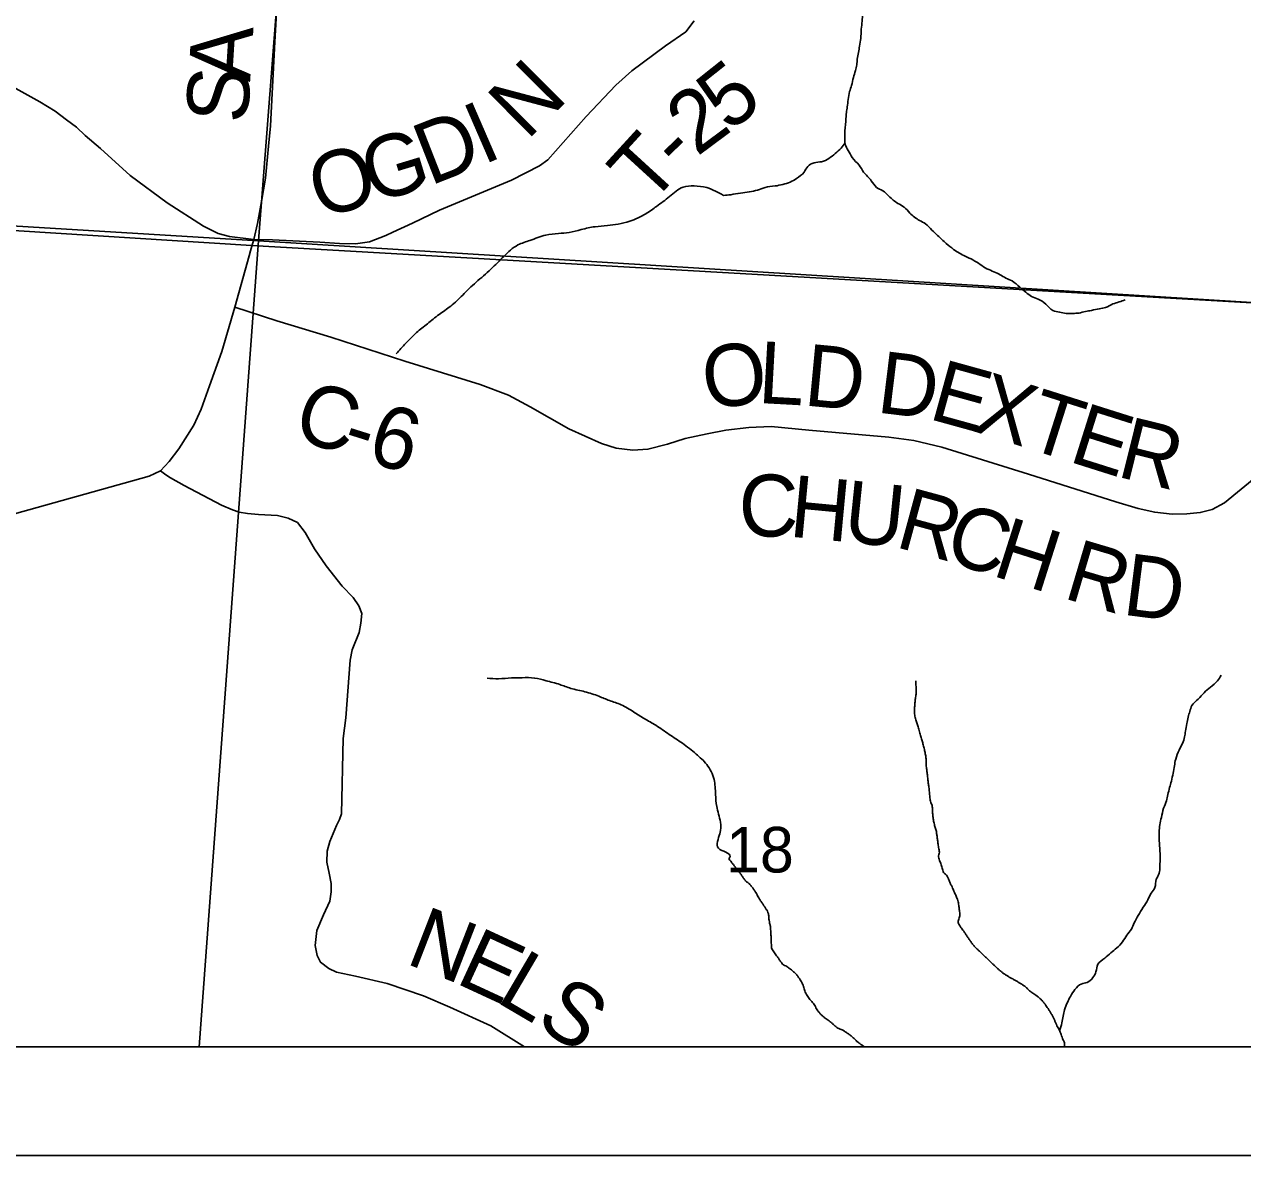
# Model space of a CAD drawing. Extents: x -13.7 to 34, y 0 to 32.3.
# Drawn here: x 28.447 to 29.565, y 14 to 15.038 of the extents above; entities that cross this region are included whole.
import ezdxf

# ---------------------------------------------------------------- set-up
doc = ezdxf.new("R2010")
doc.units = 0
for name, color, linetype in [('GM_X_Corporation', 7, 'Continuous'), ('GM_X_County_Road', 7, 'Continuous'), ('GM_X_County_Road_Text', 7, 'Continuous'), ('GM_X_Minor_River', 7, 'Continuous'), ('GM_X_Section_Text', 7, 'Continuous'), ('GM_X_Township_Road', 7, 'Continuous'), ('GM_X_Township_Road_Text', 7, 'Continuous'), ('SH_Data', 7, 'Continuous')]:
    doc.layers.add(name, color=color, linetype=linetype)

msp = doc.modelspace()

# ---------------------------------------------------------------- linework, layer by layer
at = {"layer": 'GM_X_Corporation'}
for points in [[(25.5491, 14.1), (30.3167, 14.1), (30.3167, 20.877), (30.2775, 20.8796), (29.9598, 20.9), (26.0026, 20.9)], [(27.6886, 14.8962), (28.6553, 14.8354), (29.7019, 14.7755), (30.3167, 14.7354), (30.3167, 20.877), (30.2775, 20.8796), (29.9598, 20.9), (26.0026, 20.9)]]:
    msp.add_lwpolyline(points, dxfattribs=at)
for points in [[(27.73, 15.9158), (28.7402, 15.8562), (28.6615, 14.8398), (27.6593, 14.9006)], [(28.7402, 15.8562), (28.7512, 15.8567), (29.7549, 15.7939), (29.6625, 14.7774), (28.6615, 14.8398)], [(25.5491, 14.1), (30.3167, 14.1), (30.3167, 14.7354), (29.7019, 14.7755), (28.6553, 14.8354), (27.6886, 14.8962), (26.847, 14.9399), (26.2581, 14.9774), (25.6174, 15.0182)], [(27.607, 14.1), (28.6073, 14.1), (28.6615, 14.8398), (27.6593, 14.9006)], [(28.6073, 14.1), (29.6122, 14.1), (29.6625, 14.7774), (28.6615, 14.8398)]]:
    msp.add_lwpolyline(points, close=True, dxfattribs=at)
at = {"layer": 'GM_X_County_Road'}
for points in [[(28.6572, 14.8408), (28.6606, 14.8556), (28.6643, 14.8757), (28.6682, 14.8973), (28.6709, 14.9265), (28.6726, 14.9453), (28.6766, 15.0223), (28.6792, 15.0656)], [(28.4362, 14.9809), (28.4609, 14.9672), (28.4749, 14.9588), (28.4852, 14.9507), (28.4945, 14.944), (28.5025, 14.9364), (28.5165, 14.9244), (28.5437, 14.8997), (28.5779, 14.8745), (28.611, 14.853), (28.6247, 14.8465), (28.6351, 14.8437), (28.6572, 14.8408)], [(28.6543, 14.8305), (28.6555, 14.8349), (28.6572, 14.8408)], [(28.64, 14.7787), (28.653, 14.826), (28.6543, 14.8305)], [(28.4221, 14.5848), (28.5611, 14.6235), (28.5717, 14.6286), (28.5796, 14.637), (28.5886, 14.6488), (28.6023, 14.6706), (28.6091, 14.6853), (28.6167, 14.7067), (28.6279, 14.7382), (28.64, 14.7787)], [(28.64, 14.7787), (28.6785, 14.7663), (28.7279, 14.7511), (28.796, 14.7291), (28.8651, 14.7078), (28.8913, 14.698), (28.9111, 14.6873), (28.9466, 14.6672), (28.9765, 14.6537), (28.99, 14.6495), (29.0052, 14.6474), (29.0192, 14.6483), (29.0372, 14.653), (29.0533, 14.6583), (29.0736, 14.6625), (29.0906, 14.6658), (29.1119, 14.6684), (29.1322, 14.6693), (29.1668, 14.6658), (29.2403, 14.6593), (29.2632, 14.6565), (29.2891, 14.6504), (29.3685, 14.6254), (29.4487, 14.6001), (29.4693, 14.5941), (29.4845, 14.5906), (29.5006, 14.5888), (29.5139, 14.589), (29.5263, 14.5902), (29.5373, 14.593), (29.5487, 14.5993), (29.5793, 14.6243)]]:
    msp.add_lwpolyline(points, dxfattribs=at)
at = {"layer": 'GM_X_Minor_River'}
for points in [[(29.3153, 15.2944), (29.3148, 15.2891), (29.3144, 15.283), (29.3143, 15.2754), (29.3127, 15.2686), (29.3111, 15.2625), (29.3077, 15.2557), (29.3038, 15.2493), (29.3003, 15.2441), (29.2984, 15.2384), (29.2983, 15.2262), (29.299, 15.2205), (29.2993, 15.2133), (29.3, 15.2076), (29.2999, 15.2008), (29.2987, 15.1951), (29.296, 15.1894), (29.2917, 15.1834), (29.2894, 15.1758), (29.2885, 15.1637), (29.2881, 15.1569), (29.2884, 15.1508), (29.2898, 15.1455), (29.2894, 15.139), (29.2897, 15.1337), (29.2897, 15.1272), (29.2888, 15.12), (29.2869, 15.1144), (29.2818, 15.1064), (29.2765, 15.1038), (29.2697, 15.102), (29.2621, 15.0998), (29.2541, 15.0961), (29.2483, 15.0927), (29.2422, 15.0878), (29.2353, 15.083), (29.2296, 15.0811), (29.2228, 15.0786), (29.2182, 15.0733), (29.2173, 15.0672), (29.2161, 15.0619), (29.2168, 15.0555), (29.2164, 15.0482), (29.2159, 15.0414), (29.2151, 15.0338), (29.2146, 15.0255), (29.2134, 15.0183), (29.2126, 15.0126), (29.2114, 15.0065), (29.211, 15.0012), (29.2098, 14.9959), (29.2078, 14.9895), (29.2062, 14.9823), (29.2043, 14.9766), (29.2031, 14.9694), (29.2022, 14.9626), (29.2014, 14.9573), (29.201, 14.952), (29.2001, 14.9406), (29.2, 14.9345), (29.2004, 14.9281), (29.203, 14.9227), (29.2067, 14.9162), (29.2131, 14.909), (29.2172, 14.9028), (29.2243, 14.8948), (29.2292, 14.8887), (29.2348, 14.8856), (29.2405, 14.8806), (29.2487, 14.874), (29.2544, 14.8706), (29.2597, 14.8652), (29.2687, 14.8583), (29.274, 14.8552), (29.28, 14.8494), (29.2852, 14.8445), (29.2931, 14.8372), (29.2999, 14.8318), (29.3052, 14.8283), (29.3105, 14.8256), (29.3176, 14.8221), (29.3244, 14.8179), (29.3305, 14.814), (29.3369, 14.8113), (29.3425, 14.8086), (29.3478, 14.8055), (29.3535, 14.8028), (29.3606, 14.797), (29.3663, 14.7924), (29.3715, 14.7885), (29.3776, 14.7862), (29.3844, 14.7816), (29.3911, 14.7758), (29.3972, 14.7742), (29.4033, 14.773), (29.4093, 14.773), (29.415, 14.7733)], [(27.5226, 15.1494), (27.5325, 15.144), (27.5426, 15.1352), (27.5528, 15.1283), (27.5649, 15.1222), (27.574, 15.11), (27.5765, 15.0967), (27.5795, 15.086), (27.5855, 15.0742), (27.5957, 15.0616), (27.6062, 15.0528), (27.6149, 15.0424), (27.6228, 15.0321), (27.6333, 15.0199), (27.6431, 15.0107), (27.6541, 15.0012), (27.6639, 14.9924), (27.674, 14.9828), (27.6842, 14.9721), (27.6951, 14.9614), (27.7064, 14.9484), (27.7159, 14.9381), (27.7256, 14.9262), (27.7354, 14.9163), (27.7445, 14.906), (27.7543, 14.8964), (27.7667, 14.8865), (27.7765, 14.878), (27.789, 14.87), (27.8007, 14.8619), (27.8105, 14.8562), (27.8223, 14.85), (27.8362, 14.8431), (27.8461, 14.8392), (27.8567, 14.8357), (27.8817, 14.8295), (27.8927, 14.8287), (27.9033, 14.8305), (27.914, 14.8373), (27.9239, 14.8456), (27.9365, 14.8569), (27.9483, 14.8705), (27.9575, 14.8804), (27.9671, 14.8913), (27.9774, 14.9038), (27.9896, 14.9117), (28.0037, 14.9185), (28.0166, 14.923), (28.0303, 14.9267), (28.0432, 14.9308), (28.0554, 14.9353), (28.0706, 14.9413), (28.0808, 14.9465), (28.0915, 14.9506), (28.1048, 14.9566), (28.1155, 14.9611), (28.1303, 14.9687), (28.141, 14.9728), (28.1528, 14.9799), (28.1627, 14.9863), (28.1733, 14.9923), (28.1863, 14.9995), (28.1977, 15.0063), (28.2076, 15.0111), (28.2175, 15.0156), (28.2319, 15.0205), (28.243, 15.0277), (28.2563, 15.0401), (28.2663, 15.0503), (28.2755, 15.0624), (28.2839, 15.0764), (28.2897, 15.0878), (28.295, 15.098), (28.3004, 15.1109), (28.3047, 15.1238), (28.3089, 15.1352), (28.3136, 15.1454), (28.3189, 15.1576), (28.3247, 15.1674), (28.3457, 15.1882), (28.3564, 15.1942), (28.3666, 15.1953), (28.3768, 15.1914), (28.3886, 15.1906), (28.4003, 15.1913), (28.4117, 15.1931), (28.4228, 15.1972), (28.4342, 15.2025), (28.4468, 15.2104), (28.4567, 15.2168), (28.4681, 15.2239), (28.4784, 15.2281), (28.4882, 15.228), (28.4988, 15.2264), (28.5091, 15.226), (28.5189, 15.224), (28.5671, 15.2287)], [(29.2003, 14.9296), (29.1965, 14.9247), (29.1912, 14.9198), (29.1854, 14.9153), (29.1786, 14.9123), (29.1717, 14.9113), (29.166, 14.9079), (29.1625, 14.9026), (29.1557, 14.897), (29.1499, 14.8936), (29.1431, 14.8914), (29.1359, 14.89), (29.1267, 14.8886), (29.1199, 14.8863), (29.1123, 14.8845), (29.1043, 14.8835), (29.0952, 14.882), (29.0887, 14.8813)], [(29.0887, 14.8813), (29.0732, 14.8885), (29.0615, 14.8901), (29.0516, 14.889), (29.039, 14.8803), (29.0272, 14.8713), (29.0173, 14.8645), (29.0025, 14.8577), (28.9918, 14.8551), (28.982, 14.8537), (28.9706, 14.8526), (28.958, 14.85), (28.947, 14.8474), (28.9371, 14.8464), (28.9254, 14.8449), (28.9109, 14.84), (28.8999, 14.8359), (28.8869, 14.8254), (28.8751, 14.8137), (28.8614, 14.8016), (28.8491, 14.7899), (28.8381, 14.7797), (28.8274, 14.7721), (28.8167, 14.7635), (28.8068, 14.7555), (28.7969, 14.7457), (28.7881, 14.7359)], [(29.415, 14.7733), (29.4211, 14.7748), (29.4264, 14.7758), (29.4337, 14.7773), (29.4394, 14.7784), (29.4462, 14.7817), (29.4519, 14.7836), (29.4573, 14.7854)], [(29.3972, 14.1146), (29.3993, 14.122), (29.4005, 14.1281), (29.4017, 14.1338), (29.4044, 14.1406), (29.4071, 14.1462), (29.4113, 14.1526), (29.4171, 14.1575), (29.4224, 14.159), (29.4278, 14.1635), (29.4305, 14.1688), (29.4324, 14.1756), (29.4386, 14.1812), (29.4443, 14.1861), (29.4497, 14.1906), (29.455, 14.1962), (29.4589, 14.2023), (29.4631, 14.2079), (29.4658, 14.2136), (29.4693, 14.2204), (29.4739, 14.2279), (29.4782, 14.2347), (29.4813, 14.2408), (29.4847, 14.2461), (29.486, 14.2536), (29.4887, 14.2593), (29.4891, 14.265), (29.4896, 14.2711), (29.4893, 14.2794), (29.4889, 14.2855), (29.4886, 14.2916), (29.4887, 14.2969), (29.4891, 14.3037), (29.4907, 14.3105), (29.4927, 14.3189), (29.4954, 14.3257), (29.4966, 14.3314), (29.4982, 14.3378), (29.4998, 14.3438), (29.5014, 14.351), (29.5026, 14.3579), (29.5038, 14.3639), (29.5069, 14.3722), (29.51, 14.3783), (29.512, 14.3843), (29.5128, 14.3897), (29.514, 14.3965), (29.5152, 14.4025), (29.5167, 14.4078), (29.5187, 14.4131), (29.5245, 14.4191), (29.5298, 14.4248), (29.5356, 14.43), (29.5421, 14.4357), (29.5455, 14.441)], [(29.0935, 14.2724), (29.0946, 14.2745), (29.084, 14.2822), (29.0853, 14.2955), (29.0857, 14.3061), (29.0824, 14.3206), (29.0813, 14.3316), (29.0799, 14.3453), (29.0732, 14.359), (29.0634, 14.3686), (29.0509, 14.3785), (29.0388, 14.3866), (29.0264, 14.395), (29.0158, 14.4012), (29.006, 14.4073), (28.9946, 14.4138), (28.984, 14.4177), (28.9742, 14.4216), (28.9613, 14.4258), (28.9484, 14.4289), (28.9382, 14.4324), (28.9257, 14.4359), (28.9151, 14.4383), (28.9037, 14.4387), (28.8939, 14.4384), (28.8821, 14.4377), (28.8715, 14.4381)]]:
    msp.add_spline(points, degree=3, dxfattribs=at)
for points in [[(29.4015, 14.1), (29.4016, 14.1005), (29.4017, 14.101), (29.4017, 14.1015), (29.4019, 14.1036), (29.4006, 14.1056), (29.3999, 14.1076), (29.399, 14.1099), (29.3983, 14.1122), (29.3973, 14.1144), (29.3964, 14.1164), (29.3952, 14.1182), (29.3943, 14.1202), (29.3931, 14.1227), (29.3923, 14.1253), (29.391, 14.1278), (29.3896, 14.1303), (29.3881, 14.1327), (29.3865, 14.135), (29.3852, 14.137), (29.3839, 14.1389), (29.3824, 14.1408), (29.3806, 14.143), (29.3785, 14.1448), (29.3764, 14.1465), (29.3746, 14.148), (29.3725, 14.149), (29.3707, 14.1504), (29.3686, 14.152), (29.3669, 14.1542), (29.3647, 14.1558), (29.3625, 14.1573), (29.3602, 14.1587), (29.3579, 14.16), (29.3554, 14.1615), (29.3528, 14.1628), (29.3504, 14.1643), (29.348, 14.1657), (29.3457, 14.1671), (29.3436, 14.1689), (29.3416, 14.1705), (29.3398, 14.1721), (29.3379, 14.1739), (29.3359, 14.1758), (29.3339, 14.1777), (29.3319, 14.1796), (29.3301, 14.1814), (29.3282, 14.1832), (29.3263, 14.185), (29.3242, 14.187), (29.322, 14.1891), (29.3199, 14.1911), (29.3177, 14.1933), (29.316, 14.1959), (29.3143, 14.1984), (29.3125, 14.2009), (29.3108, 14.2035), (29.3091, 14.2061), (29.3078, 14.2078), (29.3065, 14.2095), (29.3053, 14.2114), (29.3032, 14.2149), (29.3059, 14.2193), (29.3054, 14.2232), (29.3052, 14.2249), (29.305, 14.2267), (29.3047, 14.2285), (29.3044, 14.2308), (29.3041, 14.2331), (29.3033, 14.2353), (29.3026, 14.2372), (29.3019, 14.2389), (29.3011, 14.2407), (29.3002, 14.2426), (29.2993, 14.2445), (29.2985, 14.2464), (29.2971, 14.2494), (29.2958, 14.2525), (29.2944, 14.2556), (29.2935, 14.2576), (29.2911, 14.2588), (29.2903, 14.2609), (29.2895, 14.2629), (29.2891, 14.265), (29.2884, 14.267), (29.2878, 14.269), (29.2868, 14.271), (29.2862, 14.2731), (29.2857, 14.2752), (29.287, 14.2774), (29.2867, 14.2795), (29.2863, 14.2817), (29.2859, 14.2838), (29.2856, 14.286), (29.2854, 14.2878), (29.2851, 14.2896), (29.2849, 14.2913), (29.2847, 14.2931), (29.2844, 14.2949), (29.2842, 14.2967), (29.2839, 14.2985), (29.2832, 14.3002), (29.2827, 14.302), (29.2822, 14.304), (29.2817, 14.306), (29.2813, 14.3081), (29.2809, 14.3102), (29.2808, 14.3124), (29.2806, 14.3145), (29.2804, 14.3164), (29.2805, 14.3183), (29.2803, 14.3202), (29.28, 14.3223), (29.2787, 14.3242), (29.2784, 14.3263), (29.2782, 14.3283), (29.2779, 14.3304), (29.2777, 14.3324), (29.2775, 14.3347), (29.2773, 14.337), (29.277, 14.3392), (29.2768, 14.341), (29.2765, 14.3428), (29.2763, 14.3446), (29.2761, 14.3466), (29.2759, 14.3486), (29.2756, 14.3506), (29.2754, 14.3525), (29.2752, 14.3544), (29.2749, 14.3563), (29.2747, 14.3586), (29.2748, 14.3609), (29.2746, 14.3632), (29.2745, 14.3651), (29.2743, 14.367), (29.2739, 14.3689), (29.2735, 14.3709), (29.273, 14.3729), (29.2725, 14.375), (29.272, 14.3769), (29.2715, 14.3788), (29.271, 14.3807), (29.2705, 14.3827), (29.2698, 14.3847), (29.2692, 14.3868), (29.2685, 14.389), (29.268, 14.3914), (29.2673, 14.3936), (29.2668, 14.3954), (29.2661, 14.3972), (29.2655, 14.399), (29.2648, 14.4011), (29.2642, 14.4032), (29.2641, 14.4054), (29.2639, 14.4074), (29.264, 14.4095), (29.2641, 14.4115), (29.2642, 14.4135), (29.2644, 14.4156), (29.2646, 14.4176), (29.2647, 14.4196), (29.2652, 14.4216), (29.2654, 14.4236), (29.2655, 14.4257), (29.2656, 14.4277), (29.2654, 14.4297), (29.2653, 14.4317), (29.2652, 14.4338), (29.2651, 14.4358)], [(29.2179, 14.1), (29.2166, 14.1009), (29.2152, 14.1016), (29.2139, 14.1026), (29.211, 14.1048), (29.2085, 14.1076), (29.2056, 14.1099), (29.2034, 14.1117), (29.201, 14.1134), (29.1985, 14.1149), (29.1967, 14.116), (29.1945, 14.1164), (29.1928, 14.1176), (29.1906, 14.1193), (29.1886, 14.1213), (29.1864, 14.123), (29.1847, 14.1243), (29.1829, 14.1255), (29.1812, 14.1268), (29.1789, 14.1286), (29.1769, 14.1307), (29.1751, 14.133), (29.1738, 14.1347), (29.1731, 14.1369), (29.1718, 14.1387), (29.1704, 14.1406), (29.1687, 14.1422), (29.1673, 14.1441), (29.1659, 14.146), (29.1646, 14.148), (29.1636, 14.1502), (29.1627, 14.1521), (29.1626, 14.1543), (29.1617, 14.1563), (29.1608, 14.1584), (29.1597, 14.1605), (29.1584, 14.1624), (29.1567, 14.1648), (29.1549, 14.167), (29.1528, 14.1689), (29.1511, 14.1704), (29.1493, 14.1718), (29.1475, 14.1731), (29.1458, 14.1744), (29.1435, 14.1749), (29.1422, 14.1766), (29.1405, 14.1789), (29.139, 14.1812), (29.1373, 14.1835), (29.1361, 14.1853), (29.1348, 14.187), (29.1336, 14.1888), (29.1325, 14.1906), (29.1326, 14.1929), (29.1325, 14.1949), (29.1324, 14.1971), (29.1323, 14.1992), (29.1322, 14.2014), (29.1321, 14.2034), (29.132, 14.2054), (29.1319, 14.2074), (29.1317, 14.2104), (29.1309, 14.2133), (29.1305, 14.2162), (29.1302, 14.2181), (29.1303, 14.22), (29.1298, 14.2219), (29.1291, 14.2244), (29.1275, 14.2266), (29.1261, 14.2288), (29.1246, 14.2311), (29.123, 14.2333), (29.1216, 14.2356), (29.1204, 14.2375), (29.1194, 14.2395), (29.1182, 14.2414), (29.1169, 14.2436), (29.1154, 14.2458), (29.1137, 14.2479), (29.1121, 14.2499), (29.1097, 14.2512), (29.1081, 14.2532), (29.1063, 14.2556), (29.1047, 14.2582), (29.1029, 14.2605), (29.1012, 14.2625), (29.0996, 14.2646), (29.098, 14.2666), (29.0965, 14.2685), (29.095, 14.2705), (29.0935, 14.2724)]]:
    msp.add_open_spline(points, degree=3, dxfattribs=at)
at = {"layer": 'GM_X_Township_Road'}
for points in [[(28.7849, 14.8476), (28.803, 14.8559), (28.8278, 14.8678), (28.8938, 14.8953), (28.9195, 14.9084), (28.9272, 14.914), (28.9625, 14.9539), (28.9896, 14.9824), (29.0045, 14.9957), (29.0353, 15.0186), (29.054, 15.0314), (29.0617, 15.0417)], [(28.6572, 14.8408), (28.6745, 14.8407), (28.718, 14.8385), (28.736, 14.8372), (28.7507, 14.837), (28.7636, 14.8388), (28.7785, 14.8446), (28.7849, 14.8476)], [(28.9058, 14.1), (28.8751, 14.1192), (28.8374, 14.1362), (28.8132, 14.1466), (28.7798, 14.1579), (28.7506, 14.1647), (28.7334, 14.1684), (28.7263, 14.1717), (28.7187, 14.1775), (28.7155, 14.1837), (28.7136, 14.193), (28.7152, 14.2067), (28.7214, 14.2209), (28.727, 14.2337), (28.7285, 14.2422), (28.7284, 14.2499), (28.7265, 14.2593), (28.7244, 14.2695), (28.7248, 14.2795), (28.727, 14.2884), (28.7334, 14.3029), (28.7361, 14.3084), (28.7378, 14.3138), (28.7395, 14.3829), (28.7417, 14.4019), (28.7459, 14.4547), (28.7476, 14.4642), (28.754, 14.4802), (28.7557, 14.4887), (28.7565, 14.4977), (28.7538, 14.5045), (28.7485, 14.5124), (28.7385, 14.5228), (28.7238, 14.5415), (28.7131, 14.5571), (28.7044, 14.572), (28.6974, 14.5811), (28.6889, 14.5852), (28.6791, 14.5875), (28.6617, 14.5886), (28.6516, 14.5893), (28.644, 14.5906), (28.6377, 14.5929), (28.6276, 14.597), (28.5934, 14.615), (28.5807, 14.6221), (28.5767, 14.625), (28.5717, 14.6286)]]:
    msp.add_lwpolyline(points, dxfattribs=at)
at = {"layer": 'SH_Data'}
for points in [[(23.4167, 21), (30.4167, 21), (30.4167, 14), (23.4167, 14)], [(23.5167, 20.9), (30.3167, 20.9), (30.3167, 14.1), (23.5167, 14.1)]]:
    msp.add_lwpolyline(points, close=True, dxfattribs=at)

# ---------------------------------------------------------------- texts
at = {"layer": 'GM_X_County_Road_Text'}
for s, rotation, p in [('A', 86.4278, (28.6539, 14.9851)), ('S', 86.4293, (28.6515, 14.9468)), ('O', 6.9971, (29.0725, 14.6849)), ('L', 356.8527, (29.1195, 14.6909)), ('D', 354.575, (29.1613, 14.6887)), ('D', 352.9812, (29.2281, 14.6823)), ('E', 344.5615, (29.2756, 14.6766)), ('X', 342.4532, (29.316, 14.6655)), ('C', 342.1822, (28.6911, 14.6592)), ('T', 342.3755, (29.3637, 14.6504)), ('6', 343.8815, (28.7595, 14.6374)), ('E', 342.457, (29.4042, 14.6375)), ('R', 346.0516, (29.4485, 14.6236)), ('-', 342.5862, (28.7359, 14.6448)), ('C', 0.1093, (29.1026, 14.5682)), ('H', 354.6225, (29.1479, 14.5683)), ('U', 354.1357, (29.1975, 14.5636)), ('R', 344.7918, (29.2449, 14.559)), ('C', 342.4155, (29.2893, 14.5469)), ('H', 342.3726, (29.3338, 14.5328)), ('R', 343.4698, (29.3992, 14.5121)), ('D', 352.7641, (29.4538, 14.4967))]:
    msp.add_text(s, height=0.0568, rotation=rotation, dxfattribs=at).set_placement(p)
at = {"layer": 'GM_X_Section_Text'}
msp.add_text('18', height=0.04186, rotation=0, dxfattribs=at).set_placement((29.0909, 14.2599))
at = {"layer": 'GM_X_Township_Road_Text'}
for s, rotation, p in [('N', 44.9908, (28.9082, 14.9313)), ('5', 38.4624, (29.0937, 14.9386)), ('2', 36.643, (29.0641, 14.9165)), ('I', 23.4806, (28.8677, 14.909)), ('D', 21.3985, (28.819, 14.8899)), ('G', 16.859, (28.7665, 14.8737)), ('T', 47.5585, (29.0207, 14.8709)), ('-', 43.8518, (29.0487, 14.9016)), ('O', 16.074, (28.7177, 14.8597)), ('N', 338.7682, (28.7955, 14.1768)), ('E', 335.1794, (28.8412, 14.159)), ('L', 329.5529, (28.8785, 14.1419)), ('S', 326.4523, (28.9144, 14.1208))]:
    msp.add_text(s, height=0.0568, rotation=rotation, dxfattribs=at).set_placement(p)

doc.saveas('drawing.dxf')
